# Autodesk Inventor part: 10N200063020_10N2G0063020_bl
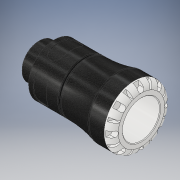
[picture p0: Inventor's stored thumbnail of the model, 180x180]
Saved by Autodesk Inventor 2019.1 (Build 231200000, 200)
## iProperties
Created: 2016-12
Part Number: 10N200063020_10N2G0063020_bl
Material: PVC-Piping
Description: PLASSON MALE ADAPTOR 63X2" SERIES 1
Document SubType Name: Modeling
Designer: KIM
Mass: 61.7504 g
Surface Area: 140.097 cm^2
Volume: 44.1074 cm^3
Density: 1.4 g/cm^3
Appearance: Black Cast
Author: KIM
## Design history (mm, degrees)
derived "10N20.ipt"
feature "Solid1::10N20.ipt" dims "ScaleForDerivedMember" = 10
tag "TaggingFeature1"
body "Solid1"
other parameters: "d0" = 175 [user parameter], "d1" = 38.64 [user parameter], "d2" = 63 [user parameter], "d3" = 78.75 [user parameter], "d4" = 103 [user parameter], "d6" = 92 [user parameter], "d8" = 87.55 [user parameter], "d13" = 9.7 [user parameter], "d14" = 9.7 [user parameter], "d15" = 0 [user parameter], "d17" = 360 deg [user parameter], "d19" = 8 deg [user parameter], "d20" = 1.26 [user parameter], "d21" = 1.26 [user parameter], "d22" = 8 deg [user parameter], "d24" = 0 [user parameter], "d26" = 360 deg [user parameter], "d32" = 0.925 [user parameter], "d33" = 10.3 [user parameter], "d34" = 59.614 [user parameter], "d35" = 7.875 [user parameter], "d38" = 26 [user parameter], "d39" = 1.78842 [user parameter], "d42" = 22.05 [user parameter], "d43" = 14.49 [user parameter], "d45" = 19.012 [user parameter], "d46" = 0 [user parameter], "d59" = 360 deg [user parameter], "d61" = 18.7425 [user parameter], "d62" = 1.26 [user parameter], "d64" = 0 [user parameter], "d65" = 1.03 [user parameter], "d69" = 2 [user parameter], "d70" = 2.625 [user parameter], "d71" = 3 [user parameter], "d73" = 1 [user parameter], "d_" = 63 [user parameter], "E_" = 103 [user parameter], "H_" = 175 [user parameter], "l_" = 92 [user parameter], "R_" = 59.614 [user parameter], "l_2" = 26 [user parameter], "d9" = 12.125 [user parameter], "d11" = 103 [user parameter], "d12" = 78.75 [user parameter]
